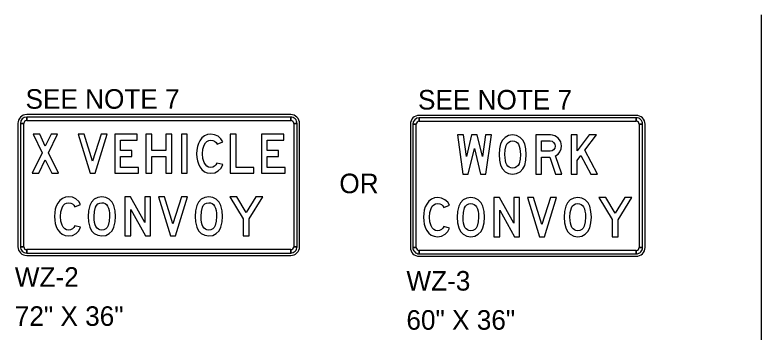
# Model space of a CAD drawing. Extents: x 1373848 to 1374003, y 380642 to 381248.
# Drawn here: x 1373931.59 to 1373954.48, y 381071.55 to 381081.28 of the extents above; entities that cross this region are included whole.
import ezdxf

# ---------------------------------------------------------------- set-up
doc = ezdxf.new("R2010")
doc.units = 0
doc.layers.add('Working Level 1', color=7, linetype='Continuous')

msp = doc.modelspace()

# ---------------------------------------------------------------- linework, layer by layer
at = {"layer": 'Working Level 1'}
for p, q in [((1373954.481, 381081.277), (1373954.481, 380977.045)), ((1373940.052, 381078.219), (1373931.952, 381078.219)), ((1373950.652, 381078.196), (1373943.992, 381078.196)), ((1373931.682, 381077.949), (1373931.682, 381074.169)), ((1373931.757, 381077.949), (1373931.862, 381077.949)), ((1373931.952, 381078.039), (1373931.952, 381078.144)), ((1373940.052, 381078.144), (1373940.052, 381078.039)), ((1373940.142, 381077.949), (1373940.247, 381077.949)), ((1373940.322, 381074.169), (1373940.322, 381077.949)), ((1373943.992, 381078.016), (1373943.992, 381078.121)), ((1373950.652, 381078.121), (1373950.652, 381078.016)), ((1373943.722, 381077.926), (1373943.722, 381074.146)), ((1373943.797, 381077.926), (1373943.902, 381077.926)), ((1373950.742, 381077.926), (1373950.847, 381077.926)), ((1373950.922, 381074.146), (1373950.922, 381077.926)), ((1373931.862, 381074.169), (1373931.757, 381074.169)), ((1373931.952, 381073.974), (1373931.952, 381074.079)), ((1373940.052, 381074.079), (1373940.052, 381073.974)), ((1373940.247, 381074.169), (1373940.142, 381074.169)), ((1373943.902, 381074.146), (1373943.797, 381074.146)), ((1373943.992, 381073.951), (1373943.992, 381074.056)), ((1373950.652, 381074.056), (1373950.652, 381073.951)), ((1373950.847, 381074.146), (1373950.742, 381074.146)), ((1373931.952, 381073.899), (1373940.052, 381073.899)), ((1373943.992, 381073.876), (1373950.652, 381073.876))]:
    msp.add_line(p, q, dxfattribs=at)
for points in [[(1373931.757, 381077.949), (1373931.757, 381074.169), (1373931.862, 381074.169), (1373931.862, 381077.949), (1373931.757, 381077.949)], [(1373940.052, 381078.144), (1373931.952, 381078.144), (1373931.952, 381078.039), (1373940.052, 381078.039), (1373940.052, 381078.144)], [(1373940.247, 381074.169), (1373940.247, 381077.949), (1373940.142, 381077.949), (1373940.142, 381074.169), (1373940.247, 381074.169)], [(1373950.652, 381078.121), (1373943.992, 381078.121), (1373943.992, 381078.016), (1373950.652, 381078.016), (1373950.652, 381078.121)], [(1373943.797, 381077.926), (1373943.797, 381074.146), (1373943.902, 381074.146), (1373943.902, 381077.926), (1373943.797, 381077.926)], [(1373950.847, 381074.146), (1373950.847, 381077.926), (1373950.742, 381077.926), (1373950.742, 381074.146), (1373950.847, 381074.146)], [(1373932.922, 381076.419), (1373932.623, 381077.047), (1373932.897, 381077.619), (1373932.697, 381077.619), (1373932.523, 381077.257), (1373932.35, 381077.619), (1373932.149, 381077.619), (1373932.422, 381077.046), (1373932.121, 381076.419), (1373932.322, 381076.419), (1373932.522, 381076.836), (1373932.721, 381076.419)], [(1373934.421, 381077.619), (1373934.231, 381077.619), (1373933.974, 381076.79), (1373933.716, 381077.619), (1373933.527, 381077.619), (1373933.899, 381076.419), (1373934.048, 381076.419)], [(1373935.378, 381076.6), (1373934.833, 381076.6), (1373934.833, 381076.94), (1373935.173, 381076.94), (1373935.173, 381077.121), (1373934.833, 381077.121), (1373934.833, 381077.438), (1373935.341, 381077.438), (1373935.341, 381077.619), (1373934.652, 381077.619), (1373934.652, 381076.419), (1373935.378, 381076.419)], [(1373936.401, 381076.419), (1373936.401, 381077.619), (1373936.22, 381077.619), (1373936.22, 381077.121), (1373935.789, 381077.121), (1373935.789, 381077.619), (1373935.608, 381077.619), (1373935.608, 381076.419), (1373935.789, 381076.419), (1373935.789, 381076.94), (1373936.22, 381076.94), (1373936.22, 381076.419)], [(1373936.877, 381076.419), (1373936.877, 381077.619), (1373936.696, 381077.619), (1373936.696, 381076.419)], [(1373937.966, 381076.685), (1373937.784, 381076.731), (1373937.757, 381076.679), (1373937.713, 381076.637), (1373937.657, 381076.609), (1373937.595, 381076.6), (1373937.532, 381076.61), (1373937.477, 381076.638), (1373937.432, 381076.686), (1373937.395, 381076.753), (1373937.358, 381076.876), (1373937.346, 381077.019), (1373937.358, 381077.163), (1373937.396, 381077.286), (1373937.434, 381077.352), (1373937.481, 381077.4), (1373937.536, 381077.428), (1373937.601, 381077.438), (1373937.66, 381077.429), (1373937.715, 381077.405), (1373937.76, 381077.365), (1373937.792, 381077.315), (1373937.966, 381077.383), (1373937.907, 381077.48), (1373937.821, 381077.555), (1373937.717, 381077.603), (1373937.603, 381077.619), (1373937.498, 381077.606), (1373937.406, 381077.569), (1373937.327, 381077.506), (1373937.261, 381077.419), (1373937.219, 381077.332), (1373937.189, 381077.237), (1373937.171, 381077.133), (1373937.165, 381077.02), (1373937.17, 381076.907), (1373937.188, 381076.803), (1373937.218, 381076.708), (1373937.26, 381076.621), (1373937.324, 381076.533), (1373937.402, 381076.47), (1373937.493, 381076.431), (1373937.597, 381076.419), (1373937.719, 381076.437), (1373937.829, 381076.493), (1373937.915, 381076.578)], [(1373938.921, 381076.419), (1373938.921, 381076.6), (1373938.377, 381076.6), (1373938.377, 381077.619), (1373938.196, 381077.619), (1373938.196, 381076.419)], [(1373939.878, 381076.6), (1373939.333, 381076.6), (1373939.333, 381076.94), (1373939.673, 381076.94), (1373939.673, 381077.121), (1373939.333, 381077.121), (1373939.333, 381077.438), (1373939.841, 381077.438), (1373939.841, 381077.619), (1373939.152, 381077.619), (1373939.152, 381076.419), (1373939.878, 381076.419)], [(1373946.209, 381077.595), (1373946.026, 381077.595), (1373945.933, 381076.938), (1373945.775, 381077.595), (1373945.6, 381077.595), (1373945.441, 381076.937), (1373945.349, 381077.595), (1373945.166, 381077.595), (1373945.334, 381076.396), (1373945.497, 381076.396), (1373945.687, 381077.185), (1373945.877, 381076.396), (1373946.041, 381076.396)], [(1373947.279, 381076.996), (1373947.266, 381077.167), (1373947.23, 381077.328), (1373947.176, 381077.436), (1373947.09, 381077.522), (1373946.981, 381077.577), (1373946.859, 381077.595), (1373946.737, 381077.577), (1373946.629, 381077.522), (1373946.544, 381077.436), (1373946.49, 381077.327), (1373946.453, 381077.166), (1373946.441, 381076.996), (1373946.453, 381076.826), (1373946.49, 381076.665), (1373946.544, 381076.556), (1373946.629, 381076.47), (1373946.737, 381076.414), (1373946.859, 381076.396), (1373946.981, 381076.414), (1373947.089, 381076.469), (1373947.175, 381076.555), (1373947.229, 381076.663), (1373947.266, 381076.824)], [(1373948.367, 381076.396), (1373948.177, 381076.956), (1373948.251, 381077.008), (1373948.309, 381077.08), (1373948.346, 381077.166), (1373948.358, 381077.258), (1373948.352, 381077.325), (1373948.333, 381077.387), (1373948.302, 381077.444), (1373948.259, 381077.496), (1373948.206, 381077.54), (1373948.149, 381077.571), (1373948.086, 381077.589), (1373948.019, 381077.595), (1373947.566, 381077.595), (1373947.566, 381076.396), (1373947.747, 381076.396), (1373947.747, 381076.916), (1373947.998, 381076.916), (1373948.176, 381076.396)], [(1373949.466, 381076.396), (1373949.077, 381077.127), (1373949.437, 381077.595), (1373949.209, 381077.595), (1373948.835, 381077.109), (1373948.835, 381077.595), (1373948.654, 381077.595), (1373948.654, 381076.396), (1373948.835, 381076.396), (1373948.835, 381076.813), (1373948.955, 381076.969), (1373949.261, 381076.396)], [(1373947.098, 381076.995), (1373947.087, 381076.85), (1373947.055, 381076.714), (1373947.026, 381076.658), (1373946.981, 381076.614), (1373946.925, 381076.586), (1373946.861, 381076.577), (1373946.804, 381076.583), (1373946.756, 381076.603), (1373946.715, 381076.635), (1373946.682, 381076.681), (1373946.655, 381076.74), (1373946.637, 381076.812), (1373946.626, 381076.897), (1373946.622, 381076.995), (1373946.633, 381077.141), (1373946.665, 381077.276), (1373946.693, 381077.332), (1373946.738, 381077.377), (1373946.795, 381077.405), (1373946.861, 381077.414), (1373946.916, 381077.408), (1373946.964, 381077.388), (1373947.005, 381077.355), (1373947.038, 381077.31), (1373947.064, 381077.251), (1373947.083, 381077.179), (1373947.094, 381077.093)], [(1373947.747, 381077.097), (1373947.747, 381077.414), (1373948.011, 381077.414), (1373948.069, 381077.402), (1373948.117, 381077.367), (1373948.15, 381077.316), (1373948.162, 381077.256), (1373948.15, 381077.195), (1373948.117, 381077.144), (1373948.069, 381077.109), (1373948.011, 381077.097)], [(1373933.606, 381074.765), (1373933.425, 381074.811), (1373933.398, 381074.759), (1373933.354, 381074.717), (1373933.298, 381074.689), (1373933.235, 381074.68), (1373933.172, 381074.69), (1373933.118, 381074.718), (1373933.072, 381074.766), (1373933.036, 381074.833), (1373932.998, 381074.956), (1373932.986, 381075.099), (1373932.999, 381075.243), (1373933.037, 381075.366), (1373933.075, 381075.432), (1373933.122, 381075.48), (1373933.177, 381075.508), (1373933.241, 381075.518), (1373933.301, 381075.509), (1373933.356, 381075.485), (1373933.401, 381075.445), (1373933.432, 381075.395), (1373933.606, 381075.463), (1373933.547, 381075.56), (1373933.462, 381075.635), (1373933.358, 381075.683), (1373933.244, 381075.699), (1373933.138, 381075.686), (1373933.046, 381075.649), (1373932.967, 381075.586), (1373932.902, 381075.499), (1373932.859, 381075.412), (1373932.829, 381075.317), (1373932.811, 381075.213), (1373932.805, 381075.1), (1373932.811, 381074.987), (1373932.829, 381074.883), (1373932.859, 381074.788), (1373932.901, 381074.701), (1373932.965, 381074.613), (1373933.043, 381074.55), (1373933.134, 381074.511), (1373933.238, 381074.499), (1373933.36, 381074.517), (1373933.47, 381074.573), (1373933.555, 381074.658)], [(1373934.674, 381075.1), (1373934.662, 381075.271), (1373934.625, 381075.431), (1373934.571, 381075.539), (1373934.485, 381075.625), (1373934.377, 381075.68), (1373934.255, 381075.699), (1373934.133, 381075.68), (1373934.025, 381075.625), (1373933.939, 381075.539), (1373933.885, 381075.43), (1373933.849, 381075.27), (1373933.837, 381075.1), (1373933.849, 381074.93), (1373933.885, 381074.769), (1373933.939, 381074.66), (1373934.025, 381074.574), (1373934.133, 381074.518), (1373934.255, 381074.499), (1373934.376, 381074.517), (1373934.485, 381074.573), (1373934.57, 381074.658), (1373934.624, 381074.767), (1373934.661, 381074.928)], [(1373935.754, 381074.499), (1373935.754, 381075.699), (1373935.573, 381075.699), (1373935.573, 381074.91), (1373935.136, 381075.699), (1373934.962, 381075.699), (1373934.962, 381074.499), (1373935.143, 381074.499), (1373935.143, 381075.313), (1373935.594, 381074.499)], [(1373936.886, 381075.699), (1373936.697, 381075.699), (1373936.439, 381074.87), (1373936.182, 381075.699), (1373935.993, 381075.699), (1373936.365, 381074.499), (1373936.514, 381074.499)], [(1373937.955, 381075.1), (1373937.943, 381075.271), (1373937.907, 381075.431), (1373937.853, 381075.539), (1373937.767, 381075.625), (1373937.658, 381075.68), (1373937.536, 381075.699), (1373937.414, 381075.68), (1373937.306, 381075.625), (1373937.22, 381075.539), (1373937.167, 381075.43), (1373937.13, 381075.27), (1373937.118, 381075.1), (1373937.13, 381074.93), (1373937.167, 381074.769), (1373937.22, 381074.66), (1373937.306, 381074.574), (1373937.414, 381074.518), (1373937.536, 381074.499), (1373937.658, 381074.517), (1373937.766, 381074.573), (1373937.851, 381074.658), (1373937.906, 381074.767), (1373937.943, 381074.928)], [(1373939.192, 381075.699), (1373938.98, 381075.699), (1373938.685, 381075.22), (1373938.397, 381075.699), (1373938.187, 381075.699), (1373938.594, 381075.025), (1373938.594, 381074.499), (1373938.775, 381074.499), (1373938.775, 381075.02)], [(1373944.926, 381074.742), (1373944.745, 381074.788), (1373944.718, 381074.735), (1373944.674, 381074.693), (1373944.618, 381074.666), (1373944.555, 381074.657), (1373944.492, 381074.666), (1373944.438, 381074.695), (1373944.392, 381074.743), (1373944.356, 381074.81), (1373944.319, 381074.933), (1373944.307, 381075.076), (1373944.319, 381075.219), (1373944.357, 381075.343), (1373944.395, 381075.409), (1373944.442, 381075.456), (1373944.497, 381075.485), (1373944.561, 381075.494), (1373944.621, 381075.486), (1373944.676, 381075.461), (1373944.721, 381075.422), (1373944.752, 381075.372), (1373944.926, 381075.44), (1373944.868, 381075.536), (1373944.782, 381075.611), (1373944.678, 381075.659), (1373944.564, 381075.675), (1373944.458, 381075.663), (1373944.366, 381075.625), (1373944.287, 381075.563), (1373944.222, 381075.475), (1373944.18, 381075.389), (1373944.149, 381075.293), (1373944.131, 381075.189), (1373944.125, 381075.076), (1373944.131, 381074.963), (1373944.149, 381074.859), (1373944.179, 381074.764), (1373944.221, 381074.678), (1373944.285, 381074.589), (1373944.363, 381074.526), (1373944.454, 381074.488), (1373944.558, 381074.476), (1373944.68, 381074.494), (1373944.79, 381074.55), (1373944.875, 381074.635)], [(1373945.994, 381075.076), (1373945.982, 381075.247), (1373945.946, 381075.408), (1373945.891, 381075.516), (1373945.805, 381075.602), (1373945.697, 381075.657), (1373945.575, 381075.675), (1373945.453, 381075.657), (1373945.345, 381075.602), (1373945.259, 381075.516), (1373945.205, 381075.407), (1373945.169, 381075.246), (1373945.157, 381075.076), (1373945.169, 381074.906), (1373945.205, 381074.745), (1373945.259, 381074.637), (1373945.345, 381074.551), (1373945.453, 381074.494), (1373945.575, 381074.476), (1373945.696, 381074.494), (1373945.805, 381074.55), (1373945.89, 381074.635), (1373945.944, 381074.743), (1373945.982, 381074.904)], [(1373947.074, 381074.476), (1373947.074, 381075.675), (1373946.893, 381075.675), (1373946.893, 381074.887), (1373946.456, 381075.675), (1373946.282, 381075.675), (1373946.282, 381074.476), (1373946.463, 381074.476), (1373946.463, 381075.29), (1373946.914, 381074.476)], [(1373948.206, 381075.675), (1373948.017, 381075.675), (1373947.759, 381074.846), (1373947.502, 381075.675), (1373947.313, 381075.675), (1373947.685, 381074.476), (1373947.834, 381074.476)], [(1373949.275, 381075.076), (1373949.263, 381075.247), (1373949.227, 381075.408), (1373949.173, 381075.516), (1373949.087, 381075.602), (1373948.978, 381075.657), (1373948.856, 381075.675), (1373948.734, 381075.657), (1373948.626, 381075.602), (1373948.54, 381075.516), (1373948.487, 381075.407), (1373948.45, 381075.246), (1373948.438, 381075.076), (1373948.45, 381074.906), (1373948.487, 381074.745), (1373948.54, 381074.637), (1373948.626, 381074.551), (1373948.734, 381074.494), (1373948.856, 381074.476), (1373948.978, 381074.494), (1373949.086, 381074.55), (1373949.171, 381074.635), (1373949.226, 381074.743), (1373949.263, 381074.904)], [(1373950.512, 381075.675), (1373950.3, 381075.675), (1373950.005, 381075.197), (1373949.717, 381075.675), (1373949.507, 381075.675), (1373949.914, 381075.001), (1373949.914, 381074.476), (1373950.095, 381074.476), (1373950.095, 381074.996)], [(1373934.493, 381075.099), (1373934.482, 381074.953), (1373934.451, 381074.818), (1373934.422, 381074.761), (1373934.377, 381074.717), (1373934.32, 381074.689), (1373934.256, 381074.68), (1373934.2, 381074.686), (1373934.151, 381074.706), (1373934.11, 381074.739), (1373934.077, 381074.785), (1373934.051, 381074.844), (1373934.032, 381074.916), (1373934.021, 381075.001), (1373934.018, 381075.099), (1373934.028, 381075.244), (1373934.06, 381075.379), (1373934.089, 381075.436), (1373934.134, 381075.48), (1373934.191, 381075.508), (1373934.256, 381075.518), (1373934.311, 381075.511), (1373934.359, 381075.492), (1373934.4, 381075.459), (1373934.434, 381075.413), (1373934.459, 381075.354), (1373934.478, 381075.282), (1373934.489, 381075.197)], [(1373937.774, 381075.099), (1373937.764, 381074.953), (1373937.732, 381074.818), (1373937.703, 381074.761), (1373937.658, 381074.717), (1373937.601, 381074.689), (1373937.537, 381074.68), (1373937.481, 381074.686), (1373937.433, 381074.706), (1373937.392, 381074.739), (1373937.358, 381074.785), (1373937.332, 381074.844), (1373937.314, 381074.916), (1373937.302, 381075.001), (1373937.299, 381075.099), (1373937.309, 381075.244), (1373937.341, 381075.379), (1373937.37, 381075.436), (1373937.415, 381075.48), (1373937.472, 381075.508), (1373937.537, 381075.518), (1373937.593, 381075.511), (1373937.641, 381075.492), (1373937.681, 381075.459), (1373937.715, 381075.413), (1373937.741, 381075.354), (1373937.759, 381075.282), (1373937.77, 381075.197)], [(1373945.813, 381075.076), (1373945.803, 381074.93), (1373945.771, 381074.794), (1373945.742, 381074.738), (1373945.697, 381074.694), (1373945.64, 381074.666), (1373945.576, 381074.657), (1373945.52, 381074.663), (1373945.471, 381074.683), (1373945.43, 381074.715), (1373945.397, 381074.761), (1373945.371, 381074.82), (1373945.353, 381074.892), (1373945.341, 381074.977), (1373945.338, 381075.076), (1373945.348, 381075.221), (1373945.38, 381075.356), (1373945.409, 381075.412), (1373945.454, 381075.457), (1373945.511, 381075.485), (1373945.576, 381075.494), (1373945.631, 381075.488), (1373945.679, 381075.468), (1373945.72, 381075.435), (1373945.754, 381075.39), (1373945.78, 381075.331), (1373945.798, 381075.259), (1373945.809, 381075.174)], [(1373949.094, 381075.076), (1373949.084, 381074.93), (1373949.052, 381074.794), (1373949.023, 381074.738), (1373948.978, 381074.694), (1373948.921, 381074.666), (1373948.857, 381074.657), (1373948.801, 381074.663), (1373948.753, 381074.683), (1373948.712, 381074.715), (1373948.678, 381074.761), (1373948.652, 381074.82), (1373948.634, 381074.892), (1373948.622, 381074.977), (1373948.619, 381075.076), (1373948.629, 381075.221), (1373948.661, 381075.356), (1373948.69, 381075.412), (1373948.735, 381075.457), (1373948.792, 381075.485), (1373948.857, 381075.494), (1373948.913, 381075.488), (1373948.961, 381075.468), (1373949.001, 381075.435), (1373949.035, 381075.39), (1373949.061, 381075.331), (1373949.079, 381075.259), (1373949.09, 381075.174)], [(1373931.952, 381073.974), (1373940.052, 381073.974), (1373940.052, 381074.079), (1373931.952, 381074.079), (1373931.952, 381073.974)], [(1373943.992, 381073.951), (1373950.652, 381073.951), (1373950.652, 381074.056), (1373943.992, 381074.056), (1373943.992, 381073.951)]]:
    msp.add_lwpolyline(points, close=True, dxfattribs=at)
for centre, radius, start, end in [((1373931.952, 381077.949), 0.27, 90.0002, 179.9998), ((1373940.052, 381077.949), 0.27, 0, 90.0002), ((1373943.992, 381077.926), 0.27, 90.0002, 179.9998), ((1373950.652, 381077.926), 0.27, 0, 90.0002), ((1373931.952, 381077.949), 0.195, 90.0002, 179.9998), ((1373931.952, 381077.949), 0.09, 90.0002, 179.9998), ((1373940.052, 381077.949), 0.195, 0, 90.0002), ((1373940.052, 381077.949), 0.09, 0, 90.0002), ((1373943.992, 381077.926), 0.195, 90.0002, 179.9998), ((1373943.992, 381077.926), 0.09, 90.0002, 179.9998), ((1373950.652, 381077.926), 0.195, 0, 90.0002), ((1373950.652, 381077.926), 0.09, 0, 90.0002), ((1373931.952, 381074.169), 0.27, 179.9998, 270.0001), ((1373931.952, 381074.169), 0.195, 179.9998, 270.0001), ((1373931.952, 381074.169), 0.09, 179.9998, 270.0001), ((1373940.052, 381074.169), 0.27, 270.0001, 0.0003), ((1373940.052, 381074.169), 0.195, 270.0001, 0.0003), ((1373940.052, 381074.169), 0.09, 270.0001, 0.0003), ((1373943.992, 381074.146), 0.27, 179.9998, 270.0001), ((1373943.992, 381074.146), 0.195, 179.9998, 270.0001), ((1373943.992, 381074.146), 0.09, 179.9998, 270.0001), ((1373950.652, 381074.146), 0.27, 270.0001, 0.0003), ((1373950.652, 381074.146), 0.195, 270.0001, 0.0003), ((1373950.652, 381074.146), 0.09, 270.0001, 0.0003)]:
    msp.add_arc(centre, radius, start, end, dxfattribs=at)

# ---------------------------------------------------------------- texts
for p in [(1373931.916, 381078.4), (1373943.956, 381078.376)]:
    msp.add_text('SEE NOTE 7 ', height=0.6, dxfattribs=at).set_placement(p)
for s, p in [('OR', (1373941.543, 381075.809)), ('WZ-2', (1373931.587, 381072.941)), ('WZ-3', (1373943.601, 381072.823)), ('72" X 36"', (1373931.587, 381071.741)), ('60" X 36"', (1373943.601, 381071.623))]:
    msp.add_text(s, height=0.6, rotation=0, dxfattribs=at).set_placement(p)

doc.saveas('drawing.dxf')
